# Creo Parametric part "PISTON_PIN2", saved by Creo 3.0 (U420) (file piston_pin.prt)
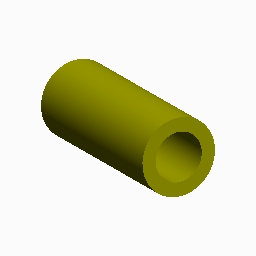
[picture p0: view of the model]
Units: millimeter Kilogram Sec (mmKs); MM, KILOGRAM, SECS

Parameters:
  MATERIAL = "ZLl09G"

Created from: PISTON.PRT

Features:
  1. datum plane "RIGHT"
  2. datum plane "TOP"
  3. datum plane "FRONT"
  4. coordinate system
  5. protrusion

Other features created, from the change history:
  round "Round 7" (2 times)
  round "Round 8" (2 times)
  round "Round 9" (2 times)
  extrusion "Extrude 8"
  mirror "Mirror 3"
  extrusion "Extrude 8 (2)"
  round "Round 10" (2 times)
  round "Round 11" (2 times)
  round "Round 12"
  round "Round 13"
  revolved cut "Revolve 1"
  chamfer "Chamfer 1"
  extruded cut "Extrude 9"
  round "Round 14"
  extrusion "Extrude 10" (2 times)
  round "Round 15"
  round "Round 16"
  round "Round 17"
  round "Round 18"
  datum plane "DTM2"
  datum axis "A_14"
  extrusion "Extrude 9"
  mirror "Mirror 4"
  mirror "Mirror 5"
  mirror "Mirror 6"

Surfaces: 5 plane, 4 cylinder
